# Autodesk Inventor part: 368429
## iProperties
Created: 2005-10
Part Number: 368429
Material: FSt
Document SubType Name: Modeling
Designer: I.Baliuc
Manufacturer: Standard
Standards Organization: Custom
Description: Halbmondring
Vendor: Seeger-Orbis GmbH
Density: 7.85 g/cm^3
Mass: 0.302243 g
Surface Area: 1.30509 cm^2
Volume: 0.0385023 cm^3
Title: Halbmondring
Company: Mayer & Müller AG Schaltgeräte
Abmessung: H10
Author: T.Messerschmitt
Revision Number: 368429
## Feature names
1. Extrusion2
